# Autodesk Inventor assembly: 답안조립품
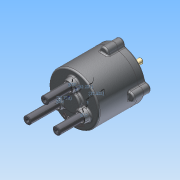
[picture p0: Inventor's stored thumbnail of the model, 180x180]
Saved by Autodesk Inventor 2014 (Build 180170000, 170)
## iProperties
Created: 2015-09
Part Number: 답안조립품
Document SubType Name: Assembly
Designer: study
Mass: 2160.14 g
Surface Area: 1801.22 cm^2
Volume: 438.509 cm^3
Density: 4.92611 g/cm^3
Author: study
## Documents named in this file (14)
- C:\Users\study\Desktop\350916V1010\답안조립품.iam
- C:\Users\study\Desktop\350916V1010\몸체.ipt
- C:\Users\study\Desktop\350916V1010\커버.ipt
- C:\Users\study\Desktop\350916V1010\오일실.ipt
- C:\Users\study\Desktop\350916V1010\M5x0.8x20.ipt
- C:\Users\study\Desktop\350916V1010\멈춤링 22 x 1.2.ipt
- C:\Users\study\Desktop\350916V1010\메인 축.ipt
- C:\Users\study\Desktop\350916V1010\베어링 NA 4900.ipt
- C:\Users\study\Desktop\350916V1010\판캠.ipt
- C:\Users\study\Desktop\350916V1010\슬라이드 축.ipt
- C:\Users\study\Desktop\350916V1010\멈춤링 10 x 1.ipt
- C:\Users\study\Desktop\350916V1010\11가변스프링.ipt
- C:\Users\study\Desktop\350916V1010\12가변스프링.ipt
- C:\Users\study\Desktop\350916V1010\13가변스프링.ipt
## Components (7 placed, 4 different names)
1. 11가변스프링:1
2. 12가변스프링:1
3. 13가변스프링:1
4. M5x0.8x20:1
5. M5x0.8x20:2
6. M5x0.8x20:3
7. M5x0.8x20:4
